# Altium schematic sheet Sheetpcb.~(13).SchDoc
size A; SheetNumber: 1; SheetTotal: 1
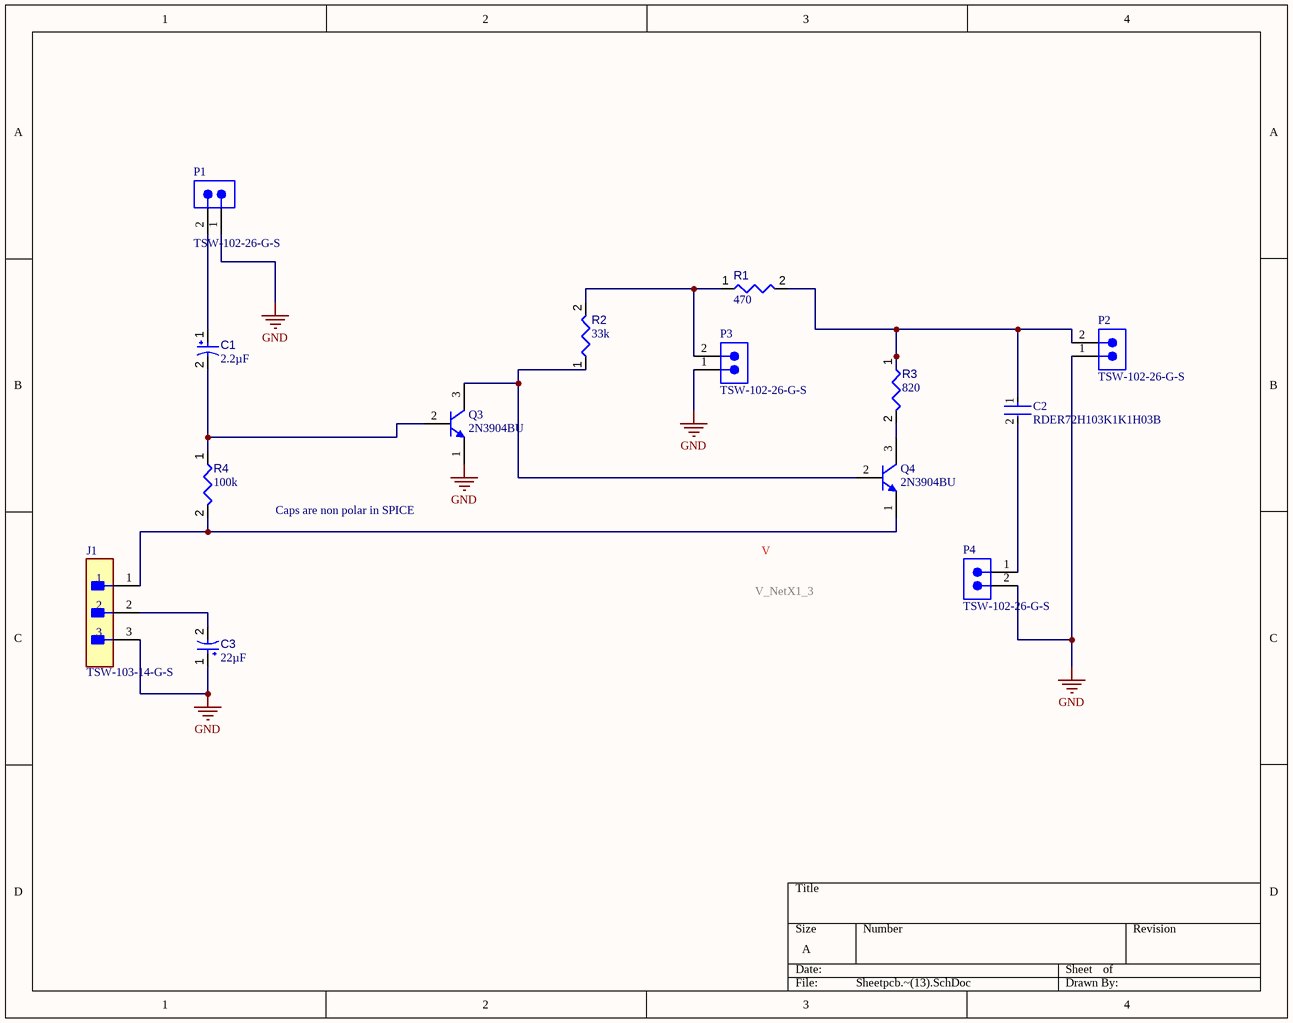
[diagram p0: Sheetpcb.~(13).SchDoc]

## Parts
C1  value 2.2µF  [CAPPR55-200-1100X500X1200]  (hidden comment: ECA1HM2R2)
C2  RDER72H103K1K1H03B  [FP-RDE1K1-MFG]
C3  value 22µF  [CAPPR55-200-1100X500X1200]  (hidden comment: ECA1HM220)
J1  TSW-103-14-G-S  [FP-TSW-103-14-G-S-MFG]
P1  TSW-102-26-G-S  [SMTC-TSW-102-26-XX-S]
P2  TSW-102-26-G-S  [SMTC-TSW-102-26-XX-S]
P3  TSW-102-26-G-S  [SMTC-TSW-102-26-XX-S]
P4  TSW-102-26-G-S  [SMTC-TSW-102-26-XX-S]
Q3  2N3904BU  [FAIR-TO-92]
Q4  2N3904BU  [FAIR-TO-92]
R1  value 470  [RESC0805(2012)_L]  (hidden comment: Resistor 470R +/-5% 0805 125 mW)
R2  value 33k  [Resistor 33K ohm]  (hidden comment: 33K Ohm Generic Through Hole Resistor)
R3  value 820  [Resistor 820 Ohm Generic]  (hidden comment: 820 Ohm Generic Resistor)
R4  value 100k  [RESA60-630X240]  (hidden comment: MFR-25FBF52-100K)

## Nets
GND: C3.1 J1.3 P1.1 P2.1 P3.1 P4.2 Q3.1(E)
NetC1_1: C1.1 P1.2
NetC1_2: C1.2 Q3.2(B) R4.1
NetC2_1: C2.1 P2.2 R1.2 R3.1
NetC2_2: C2.2 P4.1
NetC3_2: C3.2 J1.2
NetJ1_1: J1.1 Q4.1(E) R4.2
NetP3_2: P3.2 R1.1 R2.2
NetQ3_3: Q3.3(C) Q4.2(B) R2.1
NetQ4_3: Q4.3(C) R3.2

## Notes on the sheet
- Caps are non polar in SPICE

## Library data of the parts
C1 = CMP-001-00029-7: Aluminum Electrolytic Capacitor, 2.2 uF, +/- 20%, 50 V, -40 to 85 degC, 2-Pin THD, RoHS, Bulk; Manufacturer: Panasonic; Voltage Rating: 50V; Ripple Current: 20mA
C2 = CMP-06035-024341-1: Ceramic Capacitor 10nF ±10% 500V X7R Radial
C3 = CMP-001-00027-7: Aluminum Electrolytic Capacitor, 22 uF, +/- 20%, 50 V, -40 to 85 degC, 2-Pin THD, RoHS, Bulk; Manufacturer: Panasonic; Ripple Current (AC): 100mA; Voltage Rating: 50V
J1 = CMP-02766-001743-1: CONN HEADER VERT 3POS 2.54MM; Max Voltage Rating (AC): 550V; Number of Positions: 3; Max Current Rating: 7.6A; Gender: Male
P1-P4 = CMP-1024-00327-1: 0.025" SQ Post Header, Through-hole, Vertical, -55 to 125 degC, 2.54 mm Pitch, 2-Pin, Male, RoHS; Manufacturer: Samtec; Pitch: 2.54 mm
Q3 Q4 = CMP-2000-04944-1: NPN General-Purpose Amplifier, 40 V VCEO, 0.2 A, -55 to 150 degC, 2-Pin TO-92, RoHS, Bulk; Manufacturer: FairchildSemiconductor; Maximum Collector Base Voltage: 60V; Minimum DC Current Gain: 40@0.1mA@1V; Maximum Collector Emitter Voltage: 40V; Maximum DC Collector Current: 0.2A; Rad Hard: No; Maximum Operating Frequency: 300(Min)MHz; Maximum Collector Emitter Saturation Voltage: 0.2@1mA@10mA; Maximum Power Dissipation: 625mW
R1 = CMP-009-00122-3: Chip Resistor, 470 Ohms, +/-5%, 125 mW, -55 to 155 degC, 0805; Tolerance: 5%; Power: 125mW
R2 = CMP-009-00177-1: Power: 250mW
R3 = CMP-009-00179-1: Power: 250mW
R4 = CMP-009-00045-4: Axial Resistor, 100 KOhm, +/- 1%, 0.25 W, -55 to 155 degC, 2-Pin THD, RoHS, Bulk; Manufacturer: Yageo; Power: 250mW; Voltage Rating: 250V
